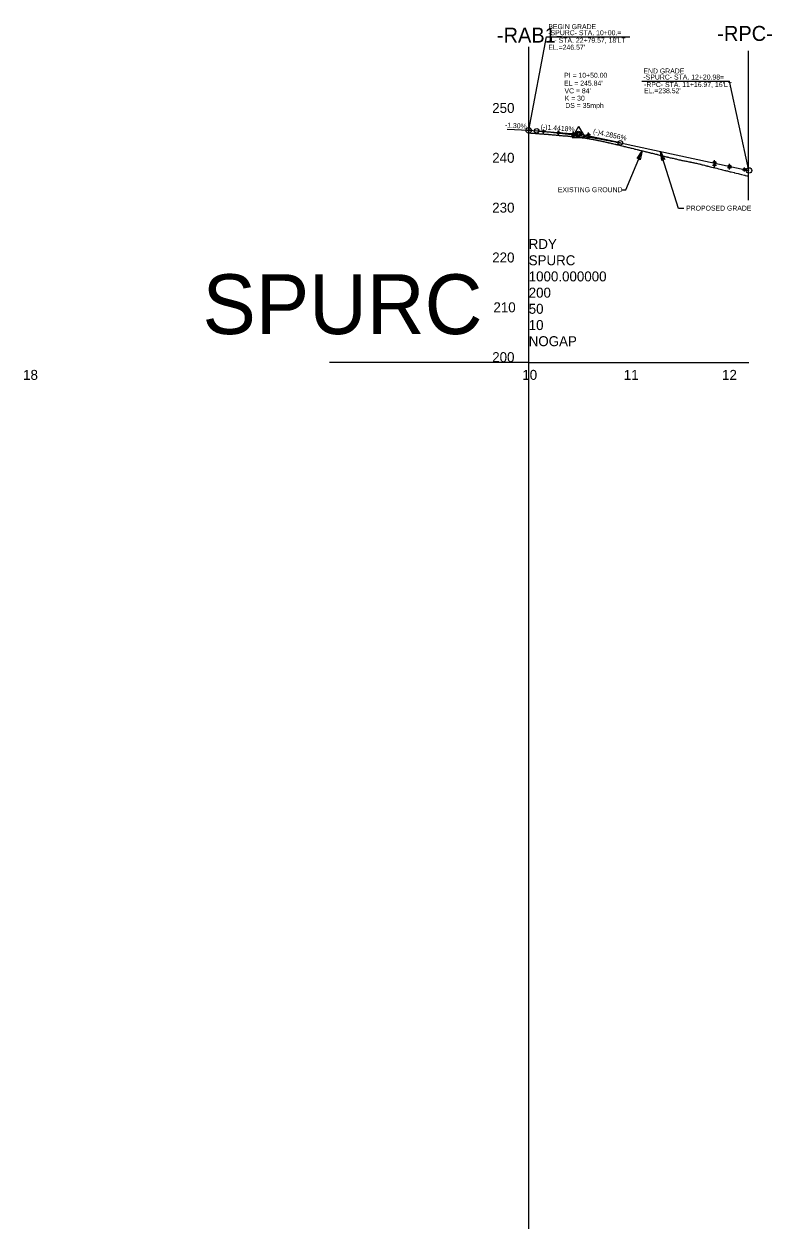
# Model space of a CAD drawing. Extents: x 2115752 to 2121174, y 562881 to 567245.
# Drawn here: x 2117491 to 2118241, y 562898 to 564107 of the extents above; entities that cross this region are included whole.
import ezdxf

# ---------------------------------------------------------------- set-up
doc = ezdxf.new("R2010")
doc.units = 0
for name, color, linetype in [('Exist Profile Cell', 7, 'Continuous'), ('Exist Vertical Profile Ground Line', 7, 'Continuous'), ('Exist Vertical Profile Horizontal Axis Label Major', 7, 'Continuous'), ('Exist Vertical Profile Vertical Axis Label', 7, 'Continuous'), ('Prop PFL VPI Symbol CELL', 7, 'Continuous'), ('Prop Terminator CELL', 7, 'Continuous'), ('Prop Vertical Profile Curve Label', 7, 'Continuous'), ('Prop Vertical Profile Grade', 7, 'Continuous'), ('Prop Vertical Profile Grade Label', 7, 'Continuous'), ('Prop VPI Label', 7, 'Continuous'), ('Scratch_Level_1', 7, 'Continuous')]:
    doc.layers.add(name, color=color, linetype=linetype)

msp = doc.modelspace()

# ---------------------------------------------------------------- linework, layer by layer
at = {"layer": 'Exist Profile Cell'}
for q in [(2117997.3, 564017.6), (2118218.3, 563767.6), (2117997.3, 563767.6)]:
    msp.add_line((2117997.3, 563767.6), q, dxfattribs=at)
at = {"layer": 'Exist Vertical Profile Ground Line'}
msp.add_lwpolyline([(2117997.3, 563997.8), (2117998.3, 563997.8), (2117999.4, 563997.7), (2118000.2, 563997.6), (2118001.3, 563997.6), (2118002.2, 563997.5), (2118003.2, 563997.5), (2118004.2, 563997.4), (2118004.7, 563997.3), (2118005.1, 563997.3), (2118006.1, 563997.3), (2118007.1, 563997.2), (2118008.1, 563997.1), (2118009, 563997.1), (2118009.4, 563997), (2118010.1, 563997), (2118010.6, 563996.9), (2118011, 563996.9), (2118012, 563996.8), (2118012.9, 563996.7), (2118013.4, 563996.7), (2118014, 563996.7), (2118014.9, 563996.6), (2118015.6, 563996.6), (2118015.9, 563996.5), (2118016.9, 563996.5), (2118017.2, 563996.4), (2118017.7, 563996.4), (2118018.8, 563996.3), (2118019.5, 563996.2), (2118020, 563996.2), (2118020.8, 563996.1), (2118021.9, 563996), (2118022.3, 563996), (2118022.7, 563995.9), (2118023.9, 563995.8), (2118024.8, 563995.7), (2118025.3, 563995.7), (2118025.7, 563995.6), (2118026.6, 563995.5), (2118027.9, 563995.4), (2118028.6, 563995.3), (2118029.7, 563995.3), (2118030.6, 563995.2), (2118031.5, 563995.1), (2118032.5, 563995.1), (2118033.5, 563995), (2118034.2, 563994.9), (2118034.5, 563994.9), (2118035.5, 563994.8), (2118036.1, 563994.8), (2118036.4, 563994.7), (2118037.4, 563994.6), (2118038, 563994.6), (2118038.4, 563994.5), (2118038.7, 563994.5), (2118039.4, 563994.4), (2118040.5, 563994.3), (2118041.4, 563994.2), (2118041.9, 563994.1), (2118042.3, 563994.1), (2118043.3, 563994), (2118044.3, 563993.8), (2118045.2, 563993.8), (2118045.8, 563993.7), (2118046.2, 563993.6), (2118046.7, 563993.6), (2118047.2, 563993.5), (2118048.3, 563993.4), (2118049.3, 563993.3), (2118050.1, 563993.1), (2118051.1, 563993), (2118052.1, 563992.9), (2118052.4, 563992.9), (2118053.1, 563992.8), (2118054.3, 563992.6), (2118055.2, 563992.5), (2118056, 563992.3), (2118056.5, 563992.2), (2118057, 563992.1), (2118057.4, 563992.1), (2118058, 563992), (2118058.3, 563991.9), (2118058.9, 563991.8), (2118059.5, 563991.7), (2118059.9, 563991.6), (2118060.4, 563991.6), (2118060.9, 563991.5), (2118062.1, 563991.2), (2118062.8, 563991.1), (2118063.8, 563991), (2118064.8, 563990.8), (2118065.4, 563990.7), (2118065.8, 563990.6), (2118066.8, 563990.4), (2118067.1, 563990.3), (2118067.7, 563990.2), (2118068.7, 563990), (2118069.2, 563989.9), (2118069.7, 563989.8), (2118070.3, 563989.7), (2118070.7, 563989.6), (2118071.7, 563989.4), (2118072.2, 563989.3), (2118072.6, 563989.2), (2118073.8, 563988.9), (2118074.7, 563988.7), (2118075.7, 563988.5), (2118076.5, 563988.3), (2118077.2, 563988.1), (2118077.5, 563988), (2118078.6, 563987.8), (2118079.7, 563987.6), (2118080.5, 563987.4), (2118080.9, 563987.3), (2118081.4, 563987.2), (2118082.4, 563986.9), (2118083.6, 563986.7), (2118084.4, 563986.5), (2118084.7, 563986.4), (2118085.4, 563986.3), (2118085.9, 563986.1), (2118086.3, 563986), (2118087.3, 563985.8), (2118088.3, 563985.5), (2118089.3, 563985.3), (2118089.8, 563985.2), (2118090.2, 563985.1), (2118090.7, 563985), (2118091.2, 563984.8), (2118092.3, 563984.6), (2118092.9, 563984.4), (2118093.2, 563984.3), (2118094.2, 563984.1), (2118094.7, 563984), (2118095.1, 563983.9), (2118096.1, 563983.6), (2118097.4, 563983.3), (2118098.1, 563983.1), (2118099, 563982.9), (2118100, 563982.7), (2118101, 563982.4), (2118102.3, 563982.1), (2118103.1, 563981.9), (2118103.9, 563981.7), (2118104.9, 563981.4), (2118106, 563981.2), (2118106.9, 563981), (2118107.4, 563980.8), (2118108.1, 563980.7), (2118108.8, 563980.5), (2118110, 563980.2), (2118110.8, 563980), (2118111.2, 563979.9), (2118111.8, 563979.8), (2118112.7, 563979.5), (2118113.7, 563979.3), (2118114.3, 563979.1), (2118114.7, 563979), (2118115.1, 563978.9), (2118115.7, 563978.8), (2118116.7, 563978.6), (2118117.7, 563978.3), (2118118.6, 563978.1), (2118119.6, 563977.8), (2118120, 563977.7), (2118120.6, 563977.6), (2118121.6, 563977.4), (2118122.5, 563977.2), (2118123, 563977.1), (2118123.5, 563976.9), (2118124.6, 563976.7), (2118125.7, 563976.4), (2118126.1, 563976.3), (2118126.4, 563976.2), (2118127.4, 563975.9), (2118128.4, 563975.7), (2118129.1, 563975.5), (2118129.4, 563975.4), (2118130.4, 563975.2), (2118131.3, 563975), (2118131.9, 563974.8), (2118132.3, 563974.7), (2118133.3, 563974.5), (2118134, 563974.3), (2118134.3, 563974.2), (2118135.3, 563974), (2118136.2, 563973.8), (2118136.6, 563973.7), (2118137.5, 563973.5), (2118138.2, 563973.3), (2118139.4, 563973), (2118140.1, 563972.9), (2118141.2, 563972.6), (2118142.2, 563972.4), (2118143.1, 563972.2), (2118144.1, 563972), (2118144.5, 563971.9), (2118145.1, 563971.7), (2118146, 563971.5), (2118147, 563971.3), (2118148, 563971), (2118148.5, 563970.9), (2118149, 563970.8), (2118149.4, 563970.7), (2118149.9, 563970.6), (2118150.3, 563970.5), (2118151, 563970.3), (2118151.9, 563970.1), (2118152.9, 563969.9), (2118154, 563969.7), (2118154.8, 563969.6), (2118155.8, 563969.4), (2118157, 563969.1), (2118157.8, 563969), (2118158.2, 563968.9), (2118158.7, 563968.8), (2118159.3, 563968.7), (2118159.7, 563968.6), (2118160.1, 563968.5), (2118160.7, 563968.4), (2118161.7, 563968.2), (2118162.3, 563968.1), (2118162.9, 563968), (2118163.3, 563967.9), (2118163.6, 563967.8), (2118164.6, 563967.6), (2118165.6, 563967.4), (2118166.6, 563967.2), (2118167.5, 563966.9), (2118168.2, 563966.7), (2118168.5, 563966.7), (2118169.5, 563966.5), (2118170.1, 563966.4), (2118170.5, 563966.3), (2118171.5, 563966), (2118172.4, 563965.8), (2118173.7, 563965.5), (2118174.4, 563965.3), (2118175.4, 563965), (2118176.3, 563964.7), (2118176.8, 563964.6), (2118177.3, 563964.5), (2118178.3, 563964.2), (2118179.3, 563964), (2118180.7, 563963.6), (2118181.2, 563963.5), (2118182.4, 563963.3), (2118183.2, 563963.1), (2118184.2, 563962.8), (2118185.9, 563962.4), (2118187.6, 563961.9), (2118188, 563961.8), (2118189.4, 563961.5), (2118190.7, 563961.1), (2118191.8, 563960.8), (2118194, 563960.3), (2118194.7, 563960.1), (2118195.6, 563959.9), (2118196.6, 563959.7), (2118197.3, 563959.5), (2118199.4, 563958.9), (2118200.1, 563958.8), (2118200.6, 563958.7), (2118203.3, 563958), (2118203.9, 563957.9), (2118205.4, 563957.5), (2118207.3, 563957), (2118208.6, 563956.7), (2118210.9, 563956.2), (2118213.9, 563955.4), (2118214.2, 563955.4), (2118214.6, 563955.3), (2118216, 563954.9), (2118217.2, 563954.7), (2118217.8, 563954.5), (2118218.3, 563954.4)], dxfattribs=at)
at = {"layer": 'Prop PFL VPI Symbol CELL'}
for p, q in [((2118047.3, 564004.3), (2118040.8, 563993.1)), ((2118047.3, 564004.3), (2118053.8, 563993.1)), ((2118040.8, 563993.1), (2118053.8, 563993.1))]:
    msp.add_line(p, q, dxfattribs=at)
for radius in [1.75, 1.2]:
    msp.add_circle((2118047.3, 563996.9), radius, dxfattribs=at)
at = {"layer": 'Prop Terminator CELL'}
for points in [[(2118106.2, 563972.2), (2118111.2, 563979.9), (2118109.1, 563971), (2118108.1, 563972.6)], [(2118130.8, 563970.2), (2118129.6, 563979.2), (2118133.8, 563971.1), (2118132, 563971.7)]]:
    msp.add_lwpolyline(points, close=True, dxfattribs=at)
at = {"layer": 'Prop Vertical Profile Curve Label'}
for centre in [(2118005.3, 563999.9), (2118089.3, 563987.9)]:
    msp.add_circle(centre, 2.25, dxfattribs=at)
at = {"layer": 'Prop Vertical Profile Grade'}
for p, q in [((2117997.3, 564000.5), (2118005.3, 563999.9)), ((2118089.3, 563987.9), (2118218.3, 563960.2))]:
    msp.add_line(p, q, dxfattribs=at)
msp.add_spline([(2118005.3, 563999.9), (2118007, 563999.8), (2118008.7, 563999.6), (2118010.3, 563999.5), (2118012, 563999.4), (2118013.7, 563999.2), (2118015.4, 563999.1), (2118017.1, 563998.9), (2118018.7, 563998.8), (2118020.4, 563998.6), (2118022.1, 563998.4), (2118023.8, 563998.3), (2118025.5, 563998.1), (2118027.1, 563997.9), (2118028.8, 563997.7), (2118030.5, 563997.5), (2118032.2, 563997.3), (2118033.9, 563997.1), (2118035.5, 563996.9), (2118037.2, 563996.7), (2118038.9, 563996.5), (2118040.6, 563996.3), (2118042.3, 563996.1), (2118043.9, 563995.8), (2118045.6, 563995.6), (2118047.3, 563995.4), (2118049, 563995.1), (2118050.7, 563994.9), (2118052.3, 563994.6), (2118054, 563994.4), (2118055.7, 563994.1), (2118057.4, 563993.8), (2118059.1, 563993.6), (2118060.7, 563993.3), (2118062.4, 563993), (2118064.1, 563992.7), (2118065.8, 563992.4), (2118067.5, 563992.1), (2118069.1, 563991.8), (2118070.8, 563991.5), (2118072.5, 563991.2), (2118074.2, 563990.9), (2118075.9, 563990.6), (2118077.5, 563990.3), (2118079.2, 563989.9), (2118080.9, 563989.6), (2118082.6, 563989.3), (2118084.3, 563988.9), (2118085.9, 563988.6), (2118087.6, 563988.2), (2118089.3, 563987.9)], degree=3, dxfattribs=at)
at = {"layer": 'Prop VPI Label'}
for p, q in [((2117997.3, 564000.5), (2118015.2, 564094.3)), ((2118015.2, 564094.3), (2118098.7, 564094.3)), ((2118110.9, 564049.9), (2118198.7, 564049.9)), ((2118218.3, 563960.2), (2118198.7, 564049.9)), ((2117975.8, 564001.6), (2117997.3, 564000.5)), ((2118005.3, 563999.9), (2118044.5, 563997.1)), ((2118089.3, 563987.9), (2118050, 563996.3))]:
    msp.add_line(p, q, dxfattribs=at)
for points in [[(2118090.5, 563940.7), (2118094.7, 563940.7), (2118111.2, 563979.9)], [(2118152.8, 563922), (2118147.5, 563922), (2118129.6, 563979.2)]]:
    msp.add_lwpolyline(points, dxfattribs=at)
for centre in [(2117997.3, 564000.5), (2118047.3, 563996.9), (2118218.3, 563960.2)]:
    msp.add_circle(centre, 2.75, dxfattribs=at)
at = {"layer": 'Scratch_Level_1'}
for p, q in [((2117997.3, 563767.6), (2117997.3, 564084.4)), ((2118217.9, 563930.3), (2118217.9, 564080.1)), ((2117995.4, 564000.5), (2117997.3, 564000.5)), ((2117997.3, 564000.5), (2117997.3, 564002.4)), ((2117997.3, 564000.5), (2117999.2, 564000.5)), ((2117997.3, 563998.5), (2117997.3, 564000.5)), ((2118010.4, 563999.5), (2118012.3, 563999.5)), ((2118010.4, 563999.2), (2118012.3, 563999.2)), ((2118012.3, 563999.5), (2118012.3, 564001.4)), ((2118012.3, 563999.2), (2118012.3, 564001.2)), ((2118012.3, 563999.5), (2118014.2, 563999.5)), ((2118012.3, 563997.6), (2118012.3, 563999.5)), ((2118012.3, 563999.2), (2118014.2, 563999.2)), ((2118012.3, 563997.3), (2118012.3, 563999.2)), ((2118025.4, 563998.3), (2118027.3, 563998.3)), ((2118025.4, 563997.5), (2118027.3, 563997.5)), ((2118027.3, 563998.3), (2118027.3, 564000.2)), ((2118027.3, 563997.5), (2118027.3, 563999.5)), ((2118027.3, 563998.3), (2118029.2, 563998.3)), ((2118027.3, 563996.4), (2118027.3, 563998.3)), ((2118027.3, 563997.5), (2118029.2, 563997.5)), ((2118027.3, 563995.6), (2118027.3, 563997.5)), ((2118040.4, 563997.2), (2118042.3, 563997.2)), ((2118040.4, 563995.5), (2118042.3, 563995.5)), ((2118042.3, 563997.2), (2118042.3, 563999.1)), ((2118042.3, 563995.5), (2118042.3, 563997.4)), ((2118042.3, 563997.2), (2118044.2, 563997.2)), ((2118042.3, 563995.2), (2118042.3, 563997.2)), ((2118042.3, 563995.5), (2118044.2, 563995.5)), ((2118042.3, 563993.5), (2118042.3, 563995.5)), ((2118055.4, 563996.2), (2118057.3, 563996.2)), ((2118055.4, 563993.5), (2118057.3, 563993.5)), ((2118057.3, 563996.2), (2118057.3, 563998.2)), ((2118057.3, 563996.2), (2118059.2, 563996.2)), ((2118057.3, 563994.3), (2118057.3, 563996.2)), ((2118057.3, 563993.5), (2118057.3, 563995.4)), ((2118057.3, 563993.5), (2118059.2, 563993.5)), ((2118057.3, 563991.5), (2118057.3, 563993.5)), ((2118181.8, 563968.6), (2118183.8, 563968.6)), ((2118183.8, 563968.6), (2118183.8, 563970.6)), ((2118183.8, 563968.6), (2118185.7, 563968.6)), ((2118183.8, 563966.7), (2118183.8, 563968.6)), ((2118183.8, 563965.5), (2118183.8, 563967.5)), ((2118181.8, 563965.5), (2118183.8, 563965.5)), ((2118183.8, 563965.5), (2118185.7, 563965.5)), ((2118183.8, 563963.6), (2118183.8, 563965.5)), ((2118196.8, 563965), (2118198.8, 563965)), ((2118196.8, 563963.1), (2118198.8, 563963.1)), ((2118198.8, 563965), (2118198.8, 563966.9)), ((2118198.8, 563963.1), (2118198.8, 563965.1)), ((2118198.8, 563965), (2118200.7, 563965)), ((2118198.8, 563963), (2118198.8, 563965)), ((2118198.8, 563963.1), (2118200.7, 563963.1)), ((2118198.8, 563961.2), (2118198.8, 563963.1)), ((2118211.8, 563961.4), (2118213.8, 563961.4)), ((2118211.8, 563960.9), (2118213.8, 563960.9)), ((2118213.8, 563961.4), (2118213.8, 563963.3)), ((2118213.8, 563960.9), (2118213.8, 563962.8)), ((2118213.8, 563961.4), (2118215.7, 563961.4)), ((2118213.8, 563959.4), (2118213.8, 563961.4)), ((2118213.8, 563960.9), (2118215.7, 563960.9)), ((2118213.8, 563959), (2118213.8, 563960.9)), ((2117997.3, 563767.6), (2117797.3, 563767.6)), ((2117997.3, 562898.2), (2117997.3, 563767.6))]:
    msp.add_line(p, q, dxfattribs=at)
for centre in [(2117997.3, 564000.5), (2118012.3, 563999.5), (2118012.3, 563999.2), (2118027.3, 563998.3), (2118027.3, 563997.5), (2118042.3, 563997.2), (2118042.3, 563995.5), (2118057.3, 563996.2), (2118057.3, 563993.5), (2118183.8, 563968.6), (2118183.8, 563965.5), (2118198.8, 563965), (2118198.8, 563963.1), (2118213.8, 563961.4), (2118213.8, 563960.9)]:
    msp.add_circle(centre, 0.949, dxfattribs=at)

# ---------------------------------------------------------------- texts
at = {"layer": 'Exist Profile Cell'}
for s, p in [('RDY', (2117997.3, 563881.4)), ('SPURC', (2117997.3, 563865.1)), ('1000.000000', (2117997.3, 563848.9)), ('200', (2117997.3, 563832.6)), ('50', (2117997.3, 563816.4)), ('10', (2117997.3, 563800.1)), ('NOGAP', (2117997.3, 563783.9))]:
    msp.add_text(s, height=10, dxfattribs=at).set_placement(p)
at = {"layer": 'Exist Vertical Profile Horizontal Axis Label Major'}
for s, p in [('18', (2117490, 563750.1)), ('10', (2117990.9, 563750.1)), ('11', (2118092.7, 563750.1)), ('12', (2118191.3, 563750.1))]:
    msp.add_text(s, height=10, dxfattribs=at).set_placement(p)
at = {"layer": 'Exist Vertical Profile Vertical Axis Label'}
for s, height, p in [('250', 10, (2117960.7, 564017.9)), ('240', 10, (2117960.7, 563967.9)), ('230', 10, (2117960.7, 563917.9)), ('220', 10, (2117960.7, 563867.9)), ('SPURC', 60, (2117670, 563796)), ('210', 10, (2117961.9, 563817.9)), ('200', 10, (2117960.7, 563767.9))]:
    msp.add_text(s, height=height, dxfattribs=at).set_placement(p)
at = {"layer": 'Prop Vertical Profile Curve Label'}
for s, p in [("VC = 84'", (2118033.2, 564037.6)), ('K = 30', (2118033.4, 564030.2)), ('DS = 35mph', (2118034, 564022.9))]:
    msp.add_text(s, height=5, dxfattribs=at).set_placement(p)
at = {"layer": 'Prop Vertical Profile Grade Label'}
for s, rotation, p in [('-1.30%', 356.5329, (2117973.3, 564003.3)), ('(-)1.4418%', 355.8768, (2118009.1, 564001.5)), ('(-)4.2856%', 347.9056, (2118061.6, 563997.2))]:
    msp.add_text(s, height=5, rotation=rotation, dxfattribs=at).set_placement(p)
at = {"layer": 'Prop VPI Label'}
for s, p in [('-SPURC- STA. 10+00.=', (2118017, 564095.9)), ('BEGIN GRADE', (2118017, 564102)), ("-L- STA. 22+79.57, 18'LT", (2118017, 564088.3)), ("EL.=246.57'", (2118017, 564081.3)), ('PI = 10+50.00', (2118032.8, 564053.2)), ('-SPURC- STA. 12+20.98=', (2118112.4, 564051.4)), ('END GRADE', (2118112.4, 564057.5)), ("EL = 245.84'", (2118032.7, 564045.3)), ("-RPC- STA. 11+16.97, 16'LT", (2118113, 564043.9)), ("EL.=238.52'", (2118113, 564037.7)), ('EXISTING GROUND', (2118026.6, 563938.4)), ('PROPOSED GRADE', (2118155.2, 563919.9))]:
    msp.add_text(s, height=5, dxfattribs=at).set_placement(p)
at = {"layer": 'Scratch_Level_1'}
for s, p in [('-RAB1-', (2117965.4, 564088.5)), ('-RPC-', (2118186.5, 564090.2))]:
    msp.add_text(s, height=15, dxfattribs=at).set_placement(p)

doc.saveas('drawing.dxf')
